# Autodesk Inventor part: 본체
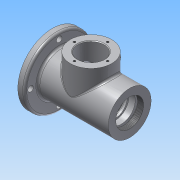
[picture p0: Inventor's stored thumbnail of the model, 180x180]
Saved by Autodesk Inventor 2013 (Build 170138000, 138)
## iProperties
Created: 2016-08
Part Number: 본체
Material: 알루미늄 6061
Document SubType Name: Modeling
Designer: Administrator
Density: 2.71 g/cm^3
Mass: 730.774 g
Surface Area: 616.446 cm^2
Volume: 269.658 cm^3
Author: Administrator
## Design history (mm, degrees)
sketch "스케치1"
  geometry: L1 (0, 0)-(115, 0); L2 (115, 0)-(115, 31); L3 (115, 31)-(112, 31); L4 (112, 31)-(112, 50); L5 (112, 50)-(105, 50); L6 (102, 47)-(102, 31); L7 (102, 31)-(0, 31); L8 (0, 31)-(0, 0); L9 (0, 21)-(9, 21); L10 (9, 21)-(9, 24); L11 (9, 24)-(12, 24); L12 (12, 24)-(12, 20); L13 (12, 20)-(21, 20); L14 (21, 20)-(21, 17.5); L15 (21, 17.5)-(24.25, 17.5); L16 (24.25, 17.5)-(24.25, 18.5); L17 (24.25, 18.5)-(26, 18.5); L18 (26, 18.5)-(26, 17.5); L19 (26, 17.5)-(36, 17.5); L20 (37, 18.5)-(37, 23); L21 (40, 26)-(72, 26); L22 (75, 23)-(75, 18.5); L23 (76, 17.5)-(85.7, 17.5); L24 (86, 17.2)-(86, 16.5); L25 (86, 16.5)-(88, 16.5); L26 (91, 13.5)-(91, 10); L27 (91, 10)-(93.7, 10); L28 (93.7, 10)-(93.7, 12.2); L29 (94, 12.5)-(100.3, 12.5); L30 (115, 0)-(115, 21); L31 (101, 12.5)-(100.3, 12.5); L32 (101, 12.5)-(101, 12.904); L33 (101, 16)-(103.089, 16); L34 (102.991, 16.711)-(115, 21); L35 (100.3, 12.5)-(101, 12.904); L36 (100.3, 12.5)-(101, 12.5); L37 (101, 12.904)-(101, 13.886); L38 (36, 17.5)-(37, 18.5); L39 (75, 18.5)-(76, 17.5); L40 (9, 21)-(9, 0); A1 r 0.3 centre (94, 12.2) between (94, 12.5) and (93.7, 12.2); A2 r 0.3 centre (85.7, 17.2) between (86, 17.2) and (85.7, 17.5); A3 r 3 centre (104, 13.886) between (102.991, 16.711) and (101, 13.886); A4 r 3 centre (72, 23) between (75, 23) and (72, 26); A5 r 3 centre (40, 23) between (40, 26) and (37, 23); A6 r 3 centre (88, 13.5) between (91, 13.5) and (88, 16.5); A7 r 3 centre (105, 47) between (105, 50) and (102, 47); 8 further points
  constraints: 80 end point, 21 point on line, 18 perpendicular, 16 tangent, 15 parallel, 14 point on circle, 7 centre point, 3 equal radius, 1 collinear, 1 horizontal
  dimensions: "d0" = 115 distance of L1.start L1.end; "d1" = 3 distance of L2.end L3.end; "d2" = 10 distance of L4.end point (102, 50); "d3" = 62 diameter of L7 L1; "d4" = 100 diameter of L5 L1; "d5" = 62 diameter of L3 L1; "d6" = 9 distance of L9.start L9.end; "d7" = 3 distance of L10.end L11.end; "d8" = 9 distance of L12.end L13.end; "d9" = 3.25 distance of L14.end L15.end; "d10" = 1.75 distance of L16.end L17.end; "d11" = 11 distance of L18.end point (37, 17.5); "d12" = 38 distance of point (37, 26) point (75, 26); "d13" = 11 distance of point (75, 17.5) point (86, 17.5); "d14" = 5 distance of L24.end point (91, 16.5); "d15" = 2.7 distance of L26.end L27.end; "d16" = 7.3 distance of point (93.7, 12.5) L31.start; "d18" = 42 diameter of L9 L1; "d19" = 48 diameter of L11 L1; "d20" = 40 diameter of L13 L1; "d21" = 35 diameter of L15 L1; "d22" = 37 diameter of L17 L1; "d23" = 35 diameter of L19 L1; "d24" = 52 diameter of L21 L1; "d25" = 35 diameter of L23 L1; "d26" = 33 diameter of L25 L1; "d27" = 20 diameter of L27 L1; "d28" = 25 diameter of L29 L1; "d29" = 21 distance of L1.end L30.end; "d30" = 0.3 radius of A1; "d31" = 0.7 distance of L31.start L29.end; "d32" = 32 diameter of L33 L1; "d33" = 3 radius of A3; "d34" = 3 radius of A4; "d35" = 30 deg angle of L31 L35; "d36" = 3 radius of A7; "d37" = 1 distance of L19.end point (37, 17.5); "d38" = 1 distance of L20.start point (37, 17.5) (= d37); "d39" = 1 distance of L22.end point (75, 17.5) (= d37); "d40" = 1 distance of L23.start point (75, 17.5) (= d39)
revolve "회전1" sketch "스케치1" stored, may be unused: angle "d41" = 90 deg
sketch "스케치2"
  geometry: C1 r 31 at (0, 0) reference; 1 further point
  constraints: 1 coincident
hole "구멍1" sketch "스케치2" at (0, 0) diameter "d42" = 40.376; stored, may be unused: countersink angle "d46" = 90 deg, drill point angle "d48" = 0 deg; dims "d43" = 9, "d44" = 4, "d45" = 2, "d47" = 9
sketch "스케치3"
  geometry: L1 (0, 0)-(-41.5, 0); C1 r 50 at (0, 0) reference; 1 further point
  constraints: 2 end point, 1 coincident, 1 horizontal
  dimensions: "d49" = 41.5 distance of L1.start L1.end
hole "구멍2" sketch "스케치3" at (-41.5, 0) diameter "d50" = 8; stored, may be unused: countersink angle "d54" = 90 deg, drill point angle "d56" = 0 deg; dims "d51" = 9, "d52" = 4, "d53" = 2, "d55" = 9
node "작업 평면1"
sketch "스케치4"
  geometry: L1 (0, -31)-(0, 31) reference; L2 (0, 0)-(56, 0); C1 r 30 at (56, 0)
  constraints: 2 end point, 1 centre point, 1 coincident, 1 perpendicular
  dimensions: "d61" = 56 distance of L2.start L2.end; "d62" = 60 diameter of C1
extrude "돌출1" join sketch "스케치4" stored distance "d63" = 10; taper "d64" = 0 deg
sketch "스케치5"
  geometry: C1 r 30 at (0, 0) reference; C2 r 19 at (0, 0); 1 further point
  constraints: 1 centre point, 1 coincident
  dimensions: "d65" = 38 diameter of C2
extrude "돌출2" cut sketch "스케치5" stored distance "d66" = 10; taper "d67" = 0 deg
sketch "스케치6"
  geometry: L1 (0, 0)-(24, 0); C1 r 30 at (0, 0) reference; 2 further points
  constraints: 2 end point, 1 coincident, 1 horizontal
  dimensions: "d68" = 24 distance of L1.start L1.end
hole "구멍3" sketch "스케치6" at (24, 0) diameter "d69" = 3.242; stored, may be unused: countersink angle "d73" = 90 deg, drill point angle "d75" = 118 deg; dims "d70" = 8, "d71" = 4, "d72" = 2, "d74" = 10
node "작업 평면2"
sketch "스케치7"
  geometry: L1 (30, 0)-(-30, 0) reference; L2 (0, 0)-(0, -10); 2 further points
  constraints: 2 end point, 1 coincident, 1 midpoint, 1 perpendicular, 1 other
  dimensions: "d79" = 10 distance of L2.start L2.end
feature "엠보싱1" sketch "스케치7" dims "d80" = 0.5, "d81" = 0
fillet "모깎기1" dims "d82" = 3
chamfer "모따기1" distance "d85" = 1; stored, may be unused: second distance "d86" = 2, angle "d87" = 45 deg
node "솔리드1"
pattern_circular "원형 패턴1" dims angle "d58" = 360 deg
pattern_circular "원형 패턴2" dims angle "d77" = 360 deg
mirror "대칭1"
other parameters: "d60" = 49
